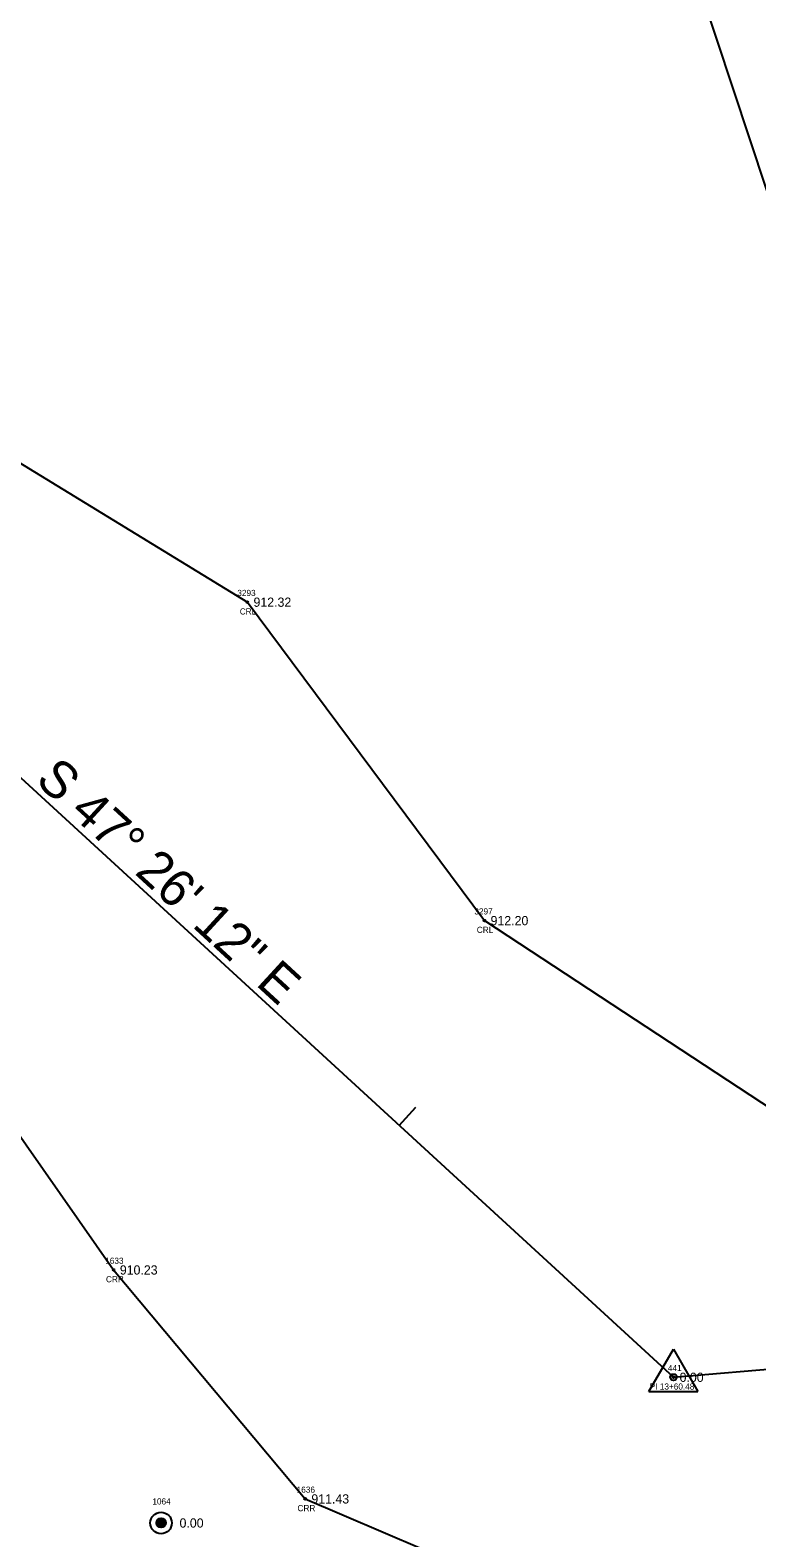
# Model space of a CAD drawing. Extents: x 1528109 to 1531398, y 1157799 to 1162548.
# Drawn here: x 1529420.7 to 1529538.8, y 1160240.8 to 1160485.7 of the extents above; entities that cross this region are included whole.
import ezdxf

# ---------------------------------------------------------------- set-up
doc = ezdxf.new("R2010")
doc.units = 0
for name, color, linetype in [('RD_EX_DV_Prop_txCode', 7, 'Continuous'), ('RD_EX_DV_PropPin', 7, 'Continuous'), ('RD_EX_H2O', 7, 'Continuous'), ('RD_EX_H2O_txCode', 7, 'Continuous'), ('RD_EX_TX_DV_Prop_ELEV', 7, 'Continuous'), ('RD_EX_TX_H2O_ELEV', 7, 'Continuous'), ('RD_EX_VEG', 7, 'Continuous'), ('RD_HC_Cl', 7, 'Continuous'), ('RD_HC_Data', 7, 'Continuous'), ('RD_HC_Data_Tic', 7, 'Continuous'), ('RD_HC_Survey_ELEV', 7, 'Continuous'), ('RD_HC_txCode', 7, 'Continuous'), ('RD_SMD_Locator', 7, 'Continuous')]:
    doc.layers.add(name, color=color, linetype=linetype)

msp = doc.modelspace()

# ---------------------------------------------------------------- linework, layer by layer
at = {"layer": 'RD_EX_DV_PropPin'}
for p, q in [((1529441.34, 1160242.87), (1529441.34, 1160243.61)), ((1529441.38, 1160242.82), (1529441.38, 1160243.67)), ((1529441.41, 1160242.77), (1529441.41, 1160243.72)), ((1529441.45, 1160242.73), (1529441.45, 1160243.76)), ((1529441.48, 1160242.69), (1529441.48, 1160243.79)), ((1529441.52, 1160242.66), (1529441.52, 1160243.83)), ((1529441.55, 1160242.63), (1529441.55, 1160243.85)), ((1529441.59, 1160242.61), (1529441.59, 1160243.88)), ((1529441.62, 1160242.59), (1529441.62, 1160243.9)), ((1529441.66, 1160242.57), (1529441.66, 1160243.92)), ((1529441.69, 1160242.55), (1529441.69, 1160243.94)), ((1529441.73, 1160242.54), (1529441.73, 1160243.95)), ((1529441.76, 1160242.52), (1529441.76, 1160243.96)), ((1529441.8, 1160242.51), (1529441.8, 1160243.98)), ((1529441.83, 1160242.5), (1529441.83, 1160243.98)), ((1529441.87, 1160242.5), (1529441.87, 1160243.99)), ((1529441.9, 1160242.49), (1529441.9, 1160244)), ((1529441.94, 1160242.49), (1529441.94, 1160244)), ((1529441.97, 1160242.48), (1529441.97, 1160244)), ((1529442.01, 1160242.48), (1529442.01, 1160244.01)), ((1529442.04, 1160242.48), (1529442.04, 1160244)), ((1529442.08, 1160242.49), (1529442.08, 1160244)), ((1529442.11, 1160242.49), (1529442.11, 1160244)), ((1529442.15, 1160242.5), (1529442.15, 1160243.99)), ((1529442.18, 1160242.5), (1529442.18, 1160243.98)), ((1529442.22, 1160242.51), (1529442.22, 1160243.98)), ((1529442.25, 1160242.52), (1529442.25, 1160243.96)), ((1529442.29, 1160242.54), (1529442.29, 1160243.95)), ((1529442.32, 1160242.55), (1529442.32, 1160243.94)), ((1529442.36, 1160242.57), (1529442.36, 1160243.92)), ((1529442.39, 1160242.59), (1529442.39, 1160243.9)), ((1529442.43, 1160242.61), (1529442.43, 1160243.88)), ((1529442.46, 1160242.63), (1529442.46, 1160243.85)), ((1529442.5, 1160242.66), (1529442.5, 1160243.83)), ((1529442.53, 1160242.69), (1529442.53, 1160243.79)), ((1529442.57, 1160242.73), (1529442.57, 1160243.76)), ((1529442.6, 1160242.77), (1529442.6, 1160243.72)), ((1529442.64, 1160242.82), (1529442.64, 1160243.67)), ((1529442.67, 1160242.87), (1529442.67, 1160243.61)), ((1529441.27, 1160243.05), (1529441.27, 1160243.44)), ((1529441.31, 1160242.95), (1529441.31, 1160243.54)), ((1529442.71, 1160242.95), (1529442.71, 1160243.54)), ((1529442.74, 1160243.05), (1529442.74, 1160243.44))]:
    msp.add_line(p, q, dxfattribs=at)
for radius in [1.75, 0.761]:
    msp.add_circle((1529442.01, 1160243.24), radius, dxfattribs=at)
at = {"layer": 'RD_EX_H2O'}
for points in [[(1529212.56, 1160420.69), (1529289.94, 1160452.31), (1529331.04, 1160457.54), (1529371.94, 1160452.7), (1529411.5, 1160420.02), (1529456.02, 1160392.77), (1529494.52, 1160341.06), (1529560.21, 1160297.91), (1529595.85, 1160295.56), (1529623.8, 1160303.23), (1529653.23, 1160315.13), (1529678.89, 1160322.7), (1529698.19, 1160309.68), (1529721.68, 1160311.69)], [(1529355.46, 1160373.84), (1529380.28, 1160350.91), (1529399.96, 1160333.39), (1529434.31, 1160284.33), (1529465.42, 1160247.15), (1529516.1, 1160225.51), (1529574.64, 1160230.43), (1529629.96, 1160232.41), (1529649.01, 1160227.21)]]:
    msp.add_lwpolyline(points, dxfattribs=at)
at = {"layer": 'RD_EX_VEG'}
msp.add_lwpolyline([(1529543.38, 1160321.88), (1529583.48, 1160329.53), (1529467.47, 1160679.92), (1529425.09, 1160802.81), (1529349.9, 1161010.59), (1529312.85, 1161137.15)], dxfattribs=at)
at = {"layer": 'RD_HC_Cl'}
for p, q in [((1529357.69, 1160420.74), (1529525.22, 1160266.9)), ((1529525.22, 1160266.9), (1529648.16, 1160277.64))]:
    msp.add_line(p, q, dxfattribs=at)
at = {"layer": 'RD_HC_Data'}
for p, q in [((1529521.25, 1160264.6), (1529525.22, 1160271.48)), ((1529525.22, 1160271.48), (1529529.19, 1160264.6)), ((1529521.25, 1160264.6), (1529529.19, 1160264.6))]:
    msp.add_line(p, q, dxfattribs=at)
msp.add_circle((1529525.22, 1160266.9), 0.529, dxfattribs=at)
at = {"layer": 'RD_HC_Data_Tic'}
msp.add_line((1529480.67, 1160307.8), (1529483.38, 1160310.75), dxfattribs=at)
at = {"layer": 'RD_SMD_Locator'}
for centre in [(1529456.02, 1160392.77), (1529494.52, 1160341.06), (1529434.31, 1160284.33), (1529525.22, 1160266.9), (1529465.42, 1160247.15), (1529442.01, 1160243.24)]:
    msp.add_circle(centre, 0.15, dxfattribs=at)

# ---------------------------------------------------------------- texts
at = {"layer": 'RD_EX_DV_Prop_txCode'}
msp.add_text('1064', height=1, dxfattribs=at).set_placement((1529440.6, 1160246.24))
at = {"layer": 'RD_EX_H2O_txCode'}
for s, p in [('3293', (1529454.39, 1160393.77)), ('CRL', (1529454.79, 1160390.77)), ('3297', (1529492.89, 1160342.06)), ('CRL', (1529493.29, 1160339.06)), ('1633', (1529432.94, 1160285.33)), ('CRR', (1529433.06, 1160282.33)), ('1636', (1529464.03, 1160248.15)), ('CRR', (1529464.17, 1160245.15))]:
    msp.add_text(s, height=1, dxfattribs=at).set_placement(p)
at = {"layer": 'RD_EX_TX_DV_Prop_ELEV'}
msp.add_text('0.00', height=1.5, dxfattribs=at).set_placement((1529445.01, 1160242.49))
at = {"layer": 'RD_EX_TX_H2O_ELEV'}
for s, p in [('912.32', (1529457.02, 1160392.02)), ('912.20', (1529495.52, 1160340.31)), ('910.23', (1529435.31, 1160283.58)), ('911.43', (1529466.42, 1160246.4))]:
    msp.add_text(s, height=1.5, dxfattribs=at).set_placement(p)
at = {"layer": 'RD_HC_Data'}
msp.add_text('S 47%%d 26\' 12" E', height=6, rotation=317.4367, dxfattribs=at).set_placement((1529421.41, 1160363.59))
at = {"layer": 'RD_HC_Survey_ELEV'}
msp.add_text('0.00', height=1.5, dxfattribs=at).set_placement((1529526.22, 1160266.15))
at = {"layer": 'RD_HC_txCode'}
for s, p in [('441', (1529524.32, 1160267.9)), ('PI 13+60.48', (1529521.37, 1160264.9))]:
    msp.add_text(s, height=1, dxfattribs=at).set_placement(p)

doc.saveas('drawing.dxf')
